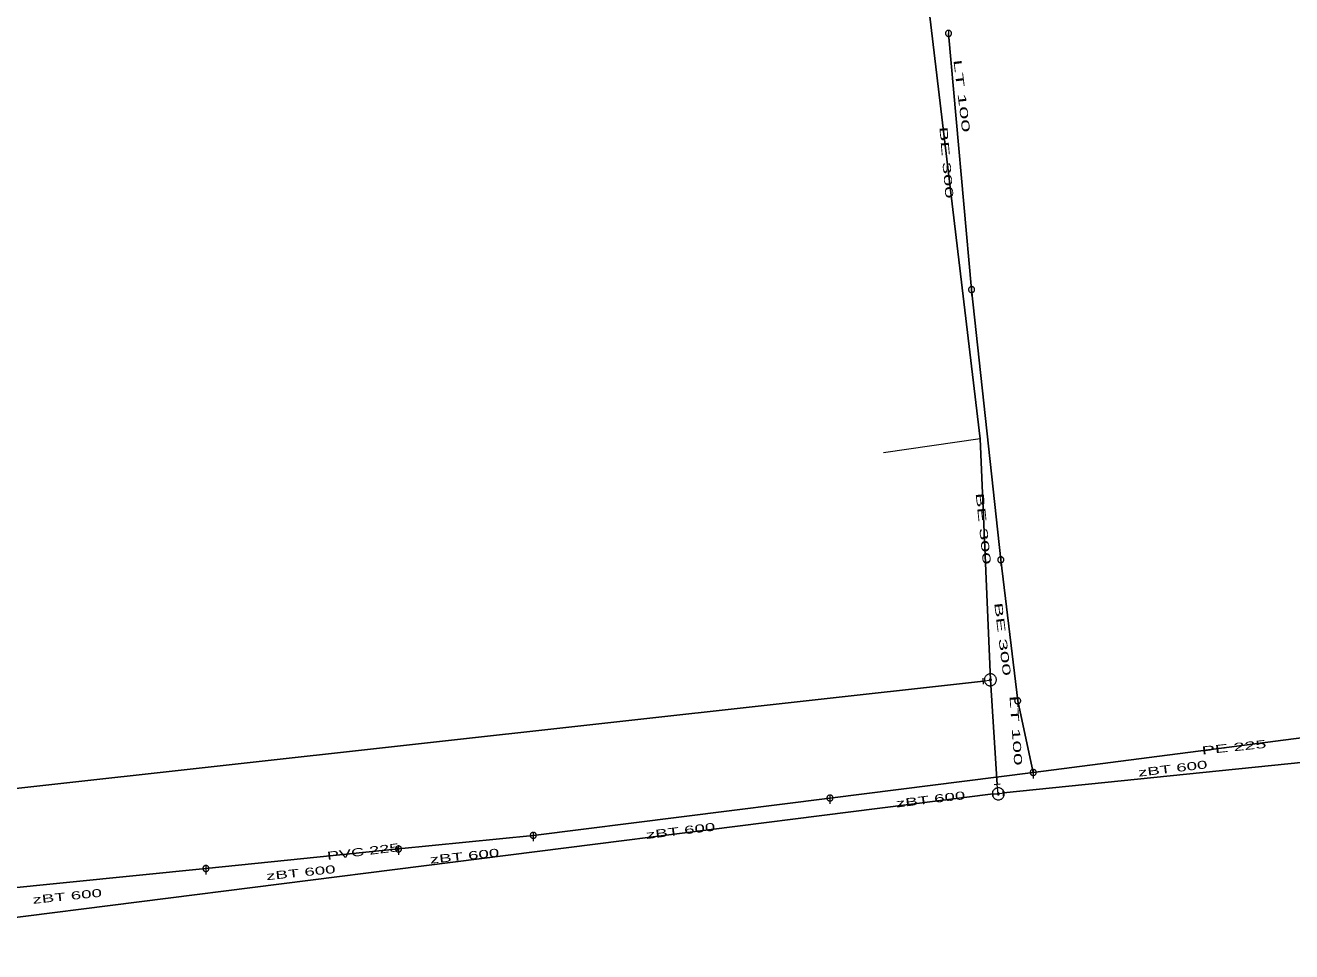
# Model space of a CAD drawing. Extents: x -687468 to -685917, y -974192 to -973456.
# Drawn here: x -686841 to -686735.6, y -973654.1 to -973576.9 of the extents above; entities that cross this region are included whole.
import ezdxf
from ezdxf.enums import TextEntityAlignment as Align

# ---------------------------------------------------------------- set-up
doc = ezdxf.new("R2010")
doc.units = 0
doc.header["$LTSCALE"] = 0.27
for name, color, linetype, lineweight in [('1', 7, 'Continuous', 13), ('13', 7, 'Continuous', 13), ('14', 7, 'Continuous', 25), ('17', 7, 'Continuous', 25), ('22', 7, 'Continuous', 13), ('34', 7, 'Continuous', 13), ('47', 7, 'Continuous', 13)]:
    doc.layers.add(name, color=color, linetype=linetype, lineweight=lineweight)

msp = doc.modelspace()

# ---------------------------------------------------------------- linework, layer by layer
at = {"layer": '13'}
msp.add_line((-686761.51, -973611.327), (-686769.549, -973612.498), dxfattribs=at)
at = {"layer": '14'}
for p, q in [((-686764.138, -973577.557), (-686762.219, -973598.897)), ((-686762.219, -973598.897), (-686759.786, -973621.405)), ((-686759.786, -973621.405), (-686758.378, -973633.151)), ((-686758.378, -973633.151), (-686757.083, -973639.12)), ((-686733.692, -973636.086), (-686757.083, -973639.12)), ((-686757.083, -973639.12), (-686774.02, -973641.251)), ((-686774.02, -973641.251), (-686798.735, -973644.361)), ((-686798.735, -973644.361), (-686809.958, -973645.497)), ((-686809.958, -973645.497), (-686826.007, -973647.121)), ((-686826.007, -973647.121), (-686848.883, -973649.437))]:
    msp.add_line(p, q, dxfattribs=at)
at = {"layer": '14', "lineweight": 13}
for p, q in [((-686761.239, -973631.509), (-686760.651, -973631.405)), ((-686759.992, -973640.903), (-686759.568, -973640.809))]:
    msp.add_line(p, q, dxfattribs=at)
msp.add_lwpolyline([(-686760.428, -973640.909), (-686759.992, -973640.903), (-686760.078, -973640.128)], dxfattribs=at)
at = {"layer": '17'}
for p, q in [((-686760.078, -973640.128), (-686760.651, -973631.405)), ((-686722.815, -973637.075), (-686759.568, -973640.809)), ((-686760.428, -973640.909), (-686864.483, -973654.051))]:
    msp.add_line(p, q, dxfattribs=at)
for points in [[(-686760.651, -973631.405), (-686761.51, -973611.327), (-686768.261, -973554.672)], [(-686937.575, -973650.962), (-686872.671, -973643.864), (-686761.239, -973631.509)]]:
    msp.add_lwpolyline(points, dxfattribs=at)
at = {"layer": '22'}
for p, q in [((-686764.138, -973577.305), (-686764.139, -973578.049)), ((-686762.218, -973598.646), (-686762.219, -973599.39)), ((-686759.785, -973621.153), (-686759.786, -973621.897)), ((-686758.377, -973632.899), (-686758.378, -973633.642)), ((-686757.082, -973638.868), (-686757.083, -973639.612)), ((-686774.019, -973640.999), (-686774.02, -973641.743)), ((-686798.734, -973644.109), (-686798.735, -973644.853)), ((-686809.957, -973645.245), (-686809.958, -973645.989)), ((-686826.006, -973646.869), (-686826.007, -973647.613))]:
    msp.add_line(p, q, dxfattribs=at)
for points in [[(-686763.887, -973577.557), (-686763.888, -973577.531), (-686763.892, -973577.505), (-686763.898, -973577.479), (-686763.908, -973577.455), (-686763.92, -973577.431), (-686763.934, -973577.409), (-686763.951, -973577.388), (-686763.969, -973577.37), (-686763.99, -973577.353), (-686764.012, -973577.339), (-686764.036, -973577.327), (-686764.06, -973577.317), (-686764.086, -973577.311), (-686764.112, -973577.307), (-686764.138, -973577.305), (-686764.164, -973577.306), (-686764.19, -973577.31), (-686764.216, -973577.316), (-686764.241, -973577.326), (-686764.264, -973577.338), (-686764.286, -973577.352), (-686764.307, -973577.369), (-686764.325, -973577.387), (-686764.342, -973577.408), (-686764.356, -973577.43), (-686764.368, -973577.454), (-686764.378, -973577.478), (-686764.385, -973577.504), (-686764.389, -973577.53), (-686764.391, -973577.556), (-686764.39, -973577.582), (-686764.386, -973577.608), (-686764.379, -973577.634), (-686764.369, -973577.659), (-686764.357, -973577.682), (-686764.343, -973577.704), (-686764.326, -973577.725), (-686764.308, -973577.743), (-686764.287, -973577.76), (-686764.265, -973577.774), (-686764.242, -973577.786), (-686764.217, -973577.796), (-686764.191, -973577.803), (-686764.165, -973577.807), (-686764.139, -973577.809), (-686764.113, -973577.808), (-686764.087, -973577.804), (-686764.061, -973577.797), (-686764.037, -973577.787), (-686764.013, -973577.775), (-686763.991, -973577.761), (-686763.97, -973577.744), (-686763.952, -973577.726), (-686763.935, -973577.705), (-686763.921, -973577.683), (-686763.909, -973577.66), (-686763.899, -973577.635), (-686763.893, -973577.609), (-686763.889, -973577.583)], [(-686761.967, -973598.898), (-686761.968, -973598.872), (-686761.972, -973598.846), (-686761.978, -973598.82), (-686761.988, -973598.796), (-686762, -973598.772), (-686762.014, -973598.75), (-686762.031, -973598.729), (-686762.049, -973598.711), (-686762.07, -973598.694), (-686762.092, -973598.68), (-686762.116, -973598.668), (-686762.14, -973598.658), (-686762.166, -973598.652), (-686762.192, -973598.648), (-686762.218, -973598.646), (-686762.244, -973598.647), (-686762.27, -973598.651), (-686762.296, -973598.657), (-686762.321, -973598.667), (-686762.344, -973598.679), (-686762.366, -973598.693), (-686762.387, -973598.71), (-686762.405, -973598.728), (-686762.422, -973598.749), (-686762.436, -973598.771), (-686762.448, -973598.795), (-686762.458, -973598.819), (-686762.465, -973598.845), (-686762.469, -973598.871), (-686762.471, -973598.897), (-686762.47, -973598.923), (-686762.466, -973598.949), (-686762.459, -973598.975), (-686762.449, -973599), (-686762.437, -973599.023), (-686762.423, -973599.045), (-686762.406, -973599.066), (-686762.388, -973599.084), (-686762.367, -973599.101), (-686762.345, -973599.115), (-686762.322, -973599.127), (-686762.297, -973599.137), (-686762.271, -973599.144), (-686762.245, -973599.148), (-686762.219, -973599.15), (-686762.193, -973599.149), (-686762.167, -973599.145), (-686762.141, -973599.138), (-686762.117, -973599.128), (-686762.093, -973599.116), (-686762.071, -973599.102), (-686762.05, -973599.085), (-686762.032, -973599.067), (-686762.015, -973599.046), (-686762.001, -973599.024), (-686761.989, -973599.001), (-686761.979, -973598.976), (-686761.973, -973598.95), (-686761.969, -973598.924)], [(-686759.534, -973621.405), (-686759.535, -973621.379), (-686759.539, -973621.353), (-686759.545, -973621.327), (-686759.555, -973621.303), (-686759.567, -973621.279), (-686759.581, -973621.257), (-686759.598, -973621.236), (-686759.616, -973621.218), (-686759.637, -973621.201), (-686759.659, -973621.187), (-686759.683, -973621.175), (-686759.707, -973621.165), (-686759.733, -973621.159), (-686759.759, -973621.155), (-686759.785, -973621.153), (-686759.811, -973621.154), (-686759.837, -973621.158), (-686759.863, -973621.164), (-686759.888, -973621.174), (-686759.911, -973621.186), (-686759.933, -973621.2), (-686759.954, -973621.217), (-686759.972, -973621.235), (-686759.989, -973621.256), (-686760.003, -973621.278), (-686760.015, -973621.302), (-686760.025, -973621.326), (-686760.032, -973621.352), (-686760.036, -973621.378), (-686760.038, -973621.404), (-686760.037, -973621.43), (-686760.033, -973621.456), (-686760.026, -973621.482), (-686760.016, -973621.507), (-686760.004, -973621.53), (-686759.99, -973621.552), (-686759.973, -973621.573), (-686759.955, -973621.591), (-686759.934, -973621.608), (-686759.912, -973621.622), (-686759.889, -973621.634), (-686759.864, -973621.644), (-686759.838, -973621.651), (-686759.812, -973621.655), (-686759.786, -973621.657), (-686759.76, -973621.656), (-686759.734, -973621.652), (-686759.708, -973621.645), (-686759.684, -973621.635), (-686759.66, -973621.623), (-686759.638, -973621.609), (-686759.617, -973621.592), (-686759.599, -973621.574), (-686759.582, -973621.553), (-686759.568, -973621.531), (-686759.556, -973621.508), (-686759.546, -973621.483), (-686759.54, -973621.457), (-686759.536, -973621.431)], [(-686758.126, -973633.151), (-686758.127, -973633.125), (-686758.131, -973633.099), (-686758.137, -973633.073), (-686758.147, -973633.049), (-686758.159, -973633.025), (-686758.173, -973633.003), (-686758.19, -973632.982), (-686758.208, -973632.964), (-686758.229, -973632.947), (-686758.251, -973632.933), (-686758.275, -973632.921), (-686758.299, -973632.911), (-686758.325, -973632.905), (-686758.351, -973632.901), (-686758.377, -973632.899), (-686758.403, -973632.9), (-686758.429, -973632.904), (-686758.455, -973632.91), (-686758.48, -973632.92), (-686758.503, -973632.932), (-686758.525, -973632.946), (-686758.546, -973632.963), (-686758.564, -973632.981), (-686758.581, -973633.002), (-686758.595, -973633.024), (-686758.607, -973633.048), (-686758.617, -973633.072), (-686758.624, -973633.098), (-686758.628, -973633.124), (-686758.63, -973633.15), (-686758.629, -973633.176), (-686758.625, -973633.202), (-686758.618, -973633.228), (-686758.608, -973633.253), (-686758.596, -973633.276), (-686758.582, -973633.298), (-686758.565, -973633.319), (-686758.547, -973633.337), (-686758.526, -973633.354), (-686758.504, -973633.368), (-686758.481, -973633.38), (-686758.456, -973633.39), (-686758.43, -973633.397), (-686758.404, -973633.401), (-686758.378, -973633.402), (-686758.352, -973633.402), (-686758.326, -973633.398), (-686758.3, -973633.391), (-686758.276, -973633.381), (-686758.252, -973633.369), (-686758.23, -973633.355), (-686758.209, -973633.338), (-686758.191, -973633.32), (-686758.174, -973633.299), (-686758.16, -973633.277), (-686758.148, -973633.254), (-686758.138, -973633.229), (-686758.132, -973633.203), (-686758.128, -973633.177)], [(-686756.831, -973639.12), (-686756.832, -973639.094), (-686756.836, -973639.068), (-686756.842, -973639.042), (-686756.852, -973639.018), (-686756.864, -973638.994), (-686756.878, -973638.972), (-686756.895, -973638.951), (-686756.913, -973638.933), (-686756.934, -973638.916), (-686756.956, -973638.902), (-686756.98, -973638.89), (-686757.004, -973638.88), (-686757.03, -973638.874), (-686757.056, -973638.87), (-686757.082, -973638.868), (-686757.108, -973638.869), (-686757.134, -973638.873), (-686757.16, -973638.879), (-686757.185, -973638.889), (-686757.208, -973638.901), (-686757.23, -973638.915), (-686757.251, -973638.932), (-686757.269, -973638.95), (-686757.286, -973638.971), (-686757.3, -973638.993), (-686757.312, -973639.017), (-686757.322, -973639.041), (-686757.329, -973639.067), (-686757.333, -973639.093), (-686757.335, -973639.119), (-686757.334, -973639.145), (-686757.33, -973639.171), (-686757.323, -973639.197), (-686757.313, -973639.222), (-686757.301, -973639.245), (-686757.287, -973639.267), (-686757.27, -973639.288), (-686757.252, -973639.306), (-686757.231, -973639.323), (-686757.209, -973639.337), (-686757.186, -973639.349), (-686757.161, -973639.359), (-686757.135, -973639.366), (-686757.109, -973639.37), (-686757.083, -973639.372), (-686757.057, -973639.371), (-686757.031, -973639.367), (-686757.005, -973639.36), (-686756.981, -973639.35), (-686756.957, -973639.338), (-686756.935, -973639.324), (-686756.914, -973639.307), (-686756.896, -973639.289), (-686756.879, -973639.268), (-686756.865, -973639.246), (-686756.853, -973639.223), (-686756.843, -973639.198), (-686756.837, -973639.172), (-686756.833, -973639.146)], [(-686773.768, -973641.251), (-686773.769, -973641.225), (-686773.773, -973641.199), (-686773.779, -973641.173), (-686773.789, -973641.149), (-686773.801, -973641.125), (-686773.815, -973641.103), (-686773.832, -973641.082), (-686773.85, -973641.064), (-686773.871, -973641.047), (-686773.893, -973641.033), (-686773.917, -973641.021), (-686773.941, -973641.011), (-686773.967, -973641.005), (-686773.993, -973641.001), (-686774.019, -973640.999), (-686774.045, -973641), (-686774.071, -973641.004), (-686774.097, -973641.01), (-686774.122, -973641.02), (-686774.145, -973641.032), (-686774.167, -973641.046), (-686774.188, -973641.063), (-686774.206, -973641.081), (-686774.223, -973641.102), (-686774.237, -973641.124), (-686774.249, -973641.148), (-686774.259, -973641.172), (-686774.266, -973641.198), (-686774.27, -973641.224), (-686774.272, -973641.25), (-686774.271, -973641.276), (-686774.267, -973641.302), (-686774.26, -973641.328), (-686774.25, -973641.353), (-686774.238, -973641.376), (-686774.224, -973641.398), (-686774.207, -973641.419), (-686774.189, -973641.437), (-686774.168, -973641.454), (-686774.146, -973641.468), (-686774.123, -973641.48), (-686774.098, -973641.49), (-686774.072, -973641.497), (-686774.046, -973641.501), (-686774.02, -973641.503), (-686773.994, -973641.502), (-686773.968, -973641.498), (-686773.942, -973641.491), (-686773.918, -973641.481), (-686773.894, -973641.469), (-686773.872, -973641.455), (-686773.851, -973641.438), (-686773.833, -973641.42), (-686773.816, -973641.399), (-686773.802, -973641.377), (-686773.79, -973641.354), (-686773.78, -973641.329), (-686773.774, -973641.303), (-686773.77, -973641.277)], [(-686798.483, -973644.361), (-686798.484, -973644.335), (-686798.488, -973644.309), (-686798.494, -973644.283), (-686798.504, -973644.259), (-686798.516, -973644.235), (-686798.53, -973644.213), (-686798.547, -973644.192), (-686798.565, -973644.174), (-686798.586, -973644.157), (-686798.608, -973644.143), (-686798.632, -973644.131), (-686798.656, -973644.121), (-686798.682, -973644.115), (-686798.708, -973644.111), (-686798.734, -973644.109), (-686798.76, -973644.11), (-686798.786, -973644.114), (-686798.812, -973644.12), (-686798.837, -973644.13), (-686798.86, -973644.142), (-686798.882, -973644.156), (-686798.903, -973644.173), (-686798.921, -973644.191), (-686798.938, -973644.212), (-686798.952, -973644.234), (-686798.964, -973644.258), (-686798.974, -973644.282), (-686798.981, -973644.308), (-686798.985, -973644.334), (-686798.987, -973644.36), (-686798.986, -973644.386), (-686798.982, -973644.412), (-686798.975, -973644.438), (-686798.965, -973644.463), (-686798.953, -973644.486), (-686798.939, -973644.508), (-686798.922, -973644.529), (-686798.904, -973644.547), (-686798.883, -973644.564), (-686798.861, -973644.578), (-686798.838, -973644.59), (-686798.813, -973644.6), (-686798.787, -973644.607), (-686798.761, -973644.611), (-686798.735, -973644.613), (-686798.709, -973644.612), (-686798.683, -973644.608), (-686798.657, -973644.601), (-686798.633, -973644.591), (-686798.609, -973644.579), (-686798.587, -973644.565), (-686798.566, -973644.548), (-686798.548, -973644.53), (-686798.531, -973644.509), (-686798.517, -973644.487), (-686798.505, -973644.464), (-686798.495, -973644.439), (-686798.489, -973644.413), (-686798.485, -973644.387)], [(-686809.706, -973645.497), (-686809.707, -973645.471), (-686809.711, -973645.445), (-686809.717, -973645.419), (-686809.727, -973645.395), (-686809.739, -973645.371), (-686809.753, -973645.349), (-686809.77, -973645.328), (-686809.788, -973645.31), (-686809.809, -973645.293), (-686809.831, -973645.279), (-686809.855, -973645.267), (-686809.879, -973645.257), (-686809.905, -973645.251), (-686809.931, -973645.247), (-686809.957, -973645.245), (-686809.983, -973645.246), (-686810.009, -973645.25), (-686810.035, -973645.256), (-686810.06, -973645.266), (-686810.083, -973645.278), (-686810.105, -973645.292), (-686810.126, -973645.309), (-686810.144, -973645.327), (-686810.161, -973645.348), (-686810.175, -973645.37), (-686810.187, -973645.394), (-686810.197, -973645.418), (-686810.204, -973645.444), (-686810.208, -973645.47), (-686810.21, -973645.496), (-686810.209, -973645.522), (-686810.205, -973645.548), (-686810.198, -973645.574), (-686810.188, -973645.599), (-686810.176, -973645.622), (-686810.162, -973645.644), (-686810.145, -973645.665), (-686810.127, -973645.683), (-686810.106, -973645.7), (-686810.084, -973645.714), (-686810.061, -973645.726), (-686810.036, -973645.736), (-686810.01, -973645.743), (-686809.984, -973645.747), (-686809.958, -973645.749), (-686809.932, -973645.748), (-686809.906, -973645.744), (-686809.88, -973645.737), (-686809.856, -973645.727), (-686809.832, -973645.715), (-686809.81, -973645.701), (-686809.789, -973645.684), (-686809.771, -973645.666), (-686809.754, -973645.645), (-686809.74, -973645.623), (-686809.728, -973645.6), (-686809.718, -973645.575), (-686809.712, -973645.549), (-686809.708, -973645.523)], [(-686825.755, -973647.121), (-686825.756, -973647.095), (-686825.76, -973647.069), (-686825.766, -973647.043), (-686825.776, -973647.019), (-686825.788, -973646.995), (-686825.802, -973646.973), (-686825.819, -973646.952), (-686825.837, -973646.934), (-686825.858, -973646.917), (-686825.88, -973646.903), (-686825.904, -973646.891), (-686825.928, -973646.881), (-686825.954, -973646.875), (-686825.98, -973646.871), (-686826.006, -973646.869), (-686826.032, -973646.87), (-686826.058, -973646.874), (-686826.084, -973646.88), (-686826.109, -973646.89), (-686826.132, -973646.902), (-686826.154, -973646.916), (-686826.175, -973646.933), (-686826.193, -973646.951), (-686826.21, -973646.972), (-686826.224, -973646.994), (-686826.236, -973647.018), (-686826.246, -973647.042), (-686826.253, -973647.068), (-686826.257, -973647.094), (-686826.259, -973647.12), (-686826.258, -973647.146), (-686826.254, -973647.172), (-686826.247, -973647.198), (-686826.237, -973647.223), (-686826.225, -973647.246), (-686826.211, -973647.268), (-686826.194, -973647.289), (-686826.176, -973647.307), (-686826.155, -973647.324), (-686826.133, -973647.338), (-686826.11, -973647.35), (-686826.085, -973647.36), (-686826.059, -973647.367), (-686826.033, -973647.371), (-686826.007, -973647.373), (-686825.981, -973647.372), (-686825.955, -973647.368), (-686825.929, -973647.361), (-686825.905, -973647.351), (-686825.881, -973647.339), (-686825.859, -973647.325), (-686825.838, -973647.308), (-686825.82, -973647.29), (-686825.803, -973647.269), (-686825.789, -973647.247), (-686825.777, -973647.224), (-686825.767, -973647.199), (-686825.761, -973647.173), (-686825.757, -973647.147)]]:
    msp.add_lwpolyline(points, close=True, dxfattribs=at)
at = {"layer": '34'}
for p, q in [((-686761.215, -973631.755), (-686761.262, -973631.262)), ((-686759.83, -973640.108), (-686760.325, -973640.147)), ((-686760.408, -973641.156), (-686760.447, -973640.661)), ((-686759.548, -973641.056), (-686759.587, -973640.561))]:
    msp.add_line(p, q, dxfattribs=at)
at = {"layer": '47'}
for points in [[(-686760.536, -973631.891), (-686760.486, -973631.876), (-686760.437, -973631.856), (-686760.391, -973631.831), (-686760.348, -973631.803), (-686760.308, -973631.768), (-686760.271, -973631.73), (-686760.24, -973631.689), (-686760.213, -973631.644), (-686760.19, -973631.598), (-686760.172, -973631.548), (-686760.159, -973631.497), (-686760.153, -973631.445), (-686760.151, -973631.393), (-686760.155, -973631.341), (-686760.164, -973631.29), (-686760.179, -973631.24), (-686760.199, -973631.191), (-686760.224, -973631.144), (-686760.252, -973631.102), (-686760.287, -973631.062), (-686760.325, -973631.025), (-686760.366, -973630.993), (-686760.411, -973630.966), (-686760.458, -973630.943), (-686760.507, -973630.926), (-686760.558, -973630.913), (-686760.61, -973630.906), (-686760.662, -973630.905), (-686760.714, -973630.909), (-686760.765, -973630.918), (-686760.815, -973630.933), (-686760.864, -973630.953), (-686760.911, -973630.977), (-686760.953, -973631.006), (-686760.993, -973631.041), (-686761.03, -973631.078), (-686761.062, -973631.12), (-686761.09, -973631.164), (-686761.112, -973631.212), (-686761.129, -973631.261), (-686761.142, -973631.312), (-686761.149, -973631.363), (-686761.15, -973631.416), (-686761.146, -973631.468), (-686761.137, -973631.519), (-686761.122, -973631.569), (-686761.102, -973631.618), (-686761.078, -973631.664), (-686761.049, -973631.707), (-686761.014, -973631.747), (-686760.977, -973631.784), (-686760.936, -973631.815), (-686760.891, -973631.843), (-686760.844, -973631.865), (-686760.794, -973631.883), (-686760.743, -973631.896), (-686760.692, -973631.902), (-686760.639, -973631.904), (-686760.587, -973631.9)], [(-686760.632, -973631.484), (-686760.623, -973631.482), (-686760.616, -973631.478), (-686760.608, -973631.475), (-686760.601, -973631.47), (-686760.594, -973631.464), (-686760.589, -973631.458), (-686760.583, -973631.451), (-686760.578, -973631.444), (-686760.575, -973631.436), (-686760.572, -973631.428), (-686760.57, -973631.419), (-686760.569, -973631.411), (-686760.569, -973631.403), (-686760.569, -973631.394), (-686760.571, -973631.386), (-686760.573, -973631.377), (-686760.577, -973631.37), (-686760.58, -973631.362), (-686760.585, -973631.355), (-686760.591, -973631.348), (-686760.597, -973631.343), (-686760.604, -973631.337), (-686760.611, -973631.332), (-686760.619, -973631.328), (-686760.627, -973631.326), (-686760.636, -973631.324), (-686760.644, -973631.323), (-686760.652, -973631.323), (-686760.661, -973631.323), (-686760.669, -973631.325), (-686760.678, -973631.327), (-686760.685, -973631.331), (-686760.693, -973631.334), (-686760.7, -973631.339), (-686760.707, -973631.345), (-686760.713, -973631.35), (-686760.718, -973631.358), (-686760.723, -973631.365), (-686760.727, -973631.373), (-686760.729, -973631.381), (-686760.731, -973631.39), (-686760.732, -973631.398), (-686760.732, -973631.406), (-686760.732, -973631.415), (-686760.73, -973631.423), (-686760.728, -973631.432), (-686760.724, -973631.439), (-686760.721, -973631.447), (-686760.716, -973631.454), (-686760.71, -973631.461), (-686760.705, -973631.467), (-686760.697, -973631.472), (-686760.69, -973631.477), (-686760.682, -973631.48), (-686760.674, -973631.483), (-686760.665, -973631.485), (-686760.657, -973631.486), (-686760.649, -973631.486), (-686760.64, -973631.486)], [(-686759.495, -973640.847), (-686759.503, -973640.796), (-686759.517, -973640.745), (-686759.536, -973640.697), (-686759.56, -973640.65), (-686759.589, -973640.606), (-686759.622, -973640.566), (-686759.66, -973640.53), (-686759.701, -973640.497), (-686759.744, -973640.468), (-686759.791, -973640.445), (-686759.84, -973640.426), (-686759.891, -973640.413), (-686759.942, -973640.405), (-686759.995, -973640.403), (-686760.047, -973640.406), (-686760.098, -973640.414), (-686760.149, -973640.428), (-686760.198, -973640.448), (-686760.244, -973640.471), (-686760.288, -973640.5), (-686760.328, -973640.533), (-686760.365, -973640.571), (-686760.398, -973640.612), (-686760.427, -973640.655), (-686760.449, -973640.702), (-686760.468, -973640.751), (-686760.482, -973640.802), (-686760.489, -973640.853), (-686760.491, -973640.906), (-686760.488, -973640.958), (-686760.48, -973641.009), (-686760.466, -973641.06), (-686760.447, -973641.109), (-686760.423, -973641.155), (-686760.394, -973641.199), (-686760.362, -973641.239), (-686760.324, -973641.277), (-686760.283, -973641.309), (-686760.239, -973641.338), (-686760.192, -973641.36), (-686760.143, -973641.379), (-686760.093, -973641.393), (-686760.041, -973641.4), (-686759.988, -973641.402), (-686759.936, -973641.399), (-686759.885, -973641.391), (-686759.834, -973641.377), (-686759.786, -973641.359), (-686759.739, -973641.334), (-686759.695, -973641.305), (-686759.655, -973641.273), (-686759.618, -973641.235), (-686759.586, -973641.194), (-686759.557, -973641.15), (-686759.534, -973641.103), (-686759.515, -973641.054), (-686759.502, -973641.004), (-686759.494, -973640.952), (-686759.492, -973640.899)], [(-686759.91, -973640.893), (-686759.911, -973640.884), (-686759.914, -973640.877), (-686759.917, -973640.869), (-686759.921, -973640.861), (-686759.925, -973640.854), (-686759.931, -973640.848), (-686759.937, -973640.841), (-686759.944, -973640.836), (-686759.951, -973640.832), (-686759.959, -973640.827), (-686759.967, -973640.824), (-686759.975, -973640.822), (-686759.983, -973640.821), (-686759.992, -973640.82), (-686760.001, -973640.821), (-686760.01, -973640.822), (-686760.017, -973640.825), (-686760.025, -973640.828), (-686760.033, -973640.832), (-686760.04, -973640.836), (-686760.046, -973640.842), (-686760.053, -973640.848), (-686760.058, -973640.855), (-686760.063, -973640.862), (-686760.067, -973640.87), (-686760.07, -973640.878), (-686760.072, -973640.886), (-686760.073, -973640.894), (-686760.074, -973640.903), (-686760.073, -973640.912), (-686760.072, -973640.921), (-686760.069, -973640.928), (-686760.066, -973640.936), (-686760.062, -973640.944), (-686760.058, -973640.951), (-686760.053, -973640.958), (-686760.046, -973640.964), (-686760.039, -973640.969), (-686760.032, -973640.974), (-686760.024, -973640.978), (-686760.016, -973640.981), (-686760.008, -973640.983), (-686760, -973640.984), (-686759.991, -973640.985), (-686759.982, -973640.984), (-686759.973, -973640.983), (-686759.966, -973640.98), (-686759.958, -973640.977), (-686759.95, -973640.973), (-686759.943, -973640.969), (-686759.936, -973640.964), (-686759.93, -973640.957), (-686759.925, -973640.95), (-686759.921, -973640.943), (-686759.916, -973640.935), (-686759.913, -973640.927), (-686759.911, -973640.919), (-686759.91, -973640.911), (-686759.909, -973640.902)]]:
    msp.add_lwpolyline(points, close=True, dxfattribs=at)

# ---------------------------------------------------------------- texts
at = {"layer": '1'}
for s, rotation, width, p in [('LT 100', 277, 2.2, (-686763.362, -973582.804)), ('BE 300', 275, 2.05, (-686764.643, -973588.344)), ('BE 300', 276, 2.05, (-686761.57, -973618.846)), ('BE 300', 277, 2.1, (-686759.962, -973628.056)), ('LT 100', 274, 2.1, (-686758.858, -973635.654)), ('PE 225', 6, 1.85, (-686740.319, -973637.348)), ('zBT 600 ', 7, 1.75, (-686745.211, -973639.095)), ('zBT 600 ', 7, 1.75, (-686765.381, -973641.666)), ('zBT 600 ', 7, 1.75, (-686786.207, -973644.287)), ('PVC 225 ', 7, 1.7, (-686812.657, -973646.015)), ('zBT 600 ', 6, 1.75, (-686804.215, -973646.393)), ('zBT 600 ', 6, 1.75, (-686817.851, -973647.773)), ('zBT 600 ', 6, 1.75, (-686837.313, -973649.743))]:
    msp.add_text(s, height=0.6667, rotation=rotation, dxfattribs=dict(at, width=width)).set_placement(p, align=Align.CENTER)

doc.saveas('drawing.dxf')
